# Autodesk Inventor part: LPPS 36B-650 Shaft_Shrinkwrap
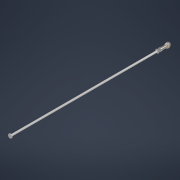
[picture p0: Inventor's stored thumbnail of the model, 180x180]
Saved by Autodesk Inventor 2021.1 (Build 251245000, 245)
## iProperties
Created: 2020-09
Part Number: LPPS 36B-650 Shaft_Shrinkwrap
Material: Generic
Document SubType Name: Modeling
Designer: J. Nielson
Density: 1 g/cm^3
Appearance: Default
Author: J. Nielson
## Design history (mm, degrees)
derived "LPPS 36B-650.iam"
body "Solid1"
node "LPPS-36B-650 ROD.ipt:1"
node "Custom Flanged Nut.ipt:1"
body "Solid2"
node "FEMALE Rod End SW.ipt:1"
body "Solid3"
node "JIS B 1181 - M8x1(4).ipt:1"
body "Solid4"
